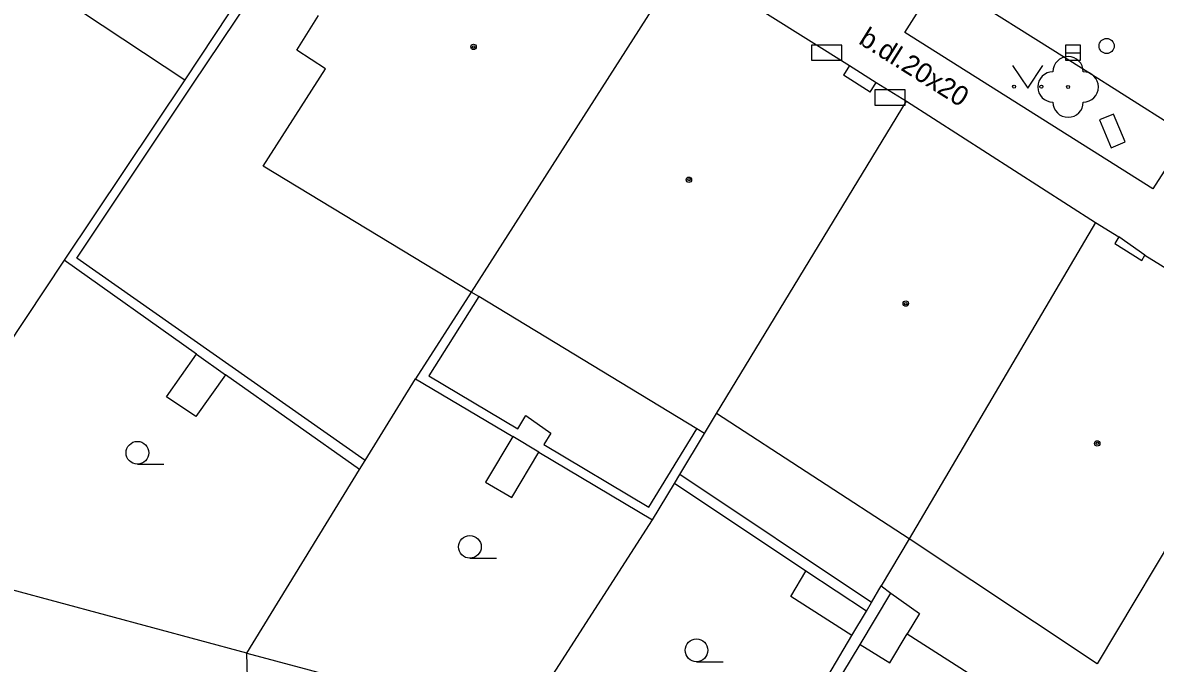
# Model space of a CAD drawing. Extents: x -595546 to -593986, y -1160845 to -1159202.
# Drawn here: x -595049.5 to -595012.16, y -1160748.75 to -1160727.63 of the extents above; entities that cross this region are included whole.
import ezdxf

# ---------------------------------------------------------------- set-up
doc = ezdxf.new("R2010")
doc.units = 0
for name, color, linetype in [('DOP - kresba z DSPS bez souradnic', 7, 'Continuous'), ('DOP - rozhrani ploch obecne', 7, 'Continuous'), ('Level 22', 7, 'Continuous'), ('Level 24', 7, 'Continuous'), ('Level 27', 7, 'Continuous'), ('Level 28', 7, 'Continuous'), ('Level 36', 7, 'Continuous'), ('Level 39', 7, 'Continuous'), ('TM - budovy zdene_ betonove - NP', 7, 'Continuous'), ('TM - budovy zdene_ betonove - VP', 7, 'Continuous'), ('TM - chodniky - VP', 7, 'Continuous'), ('TM - komunikace - VP', 7, 'Continuous'), ('TM - plot drateny_ kovovy - VP', 7, 'Continuous'), ('TM - podezdivka plotu - VP', 7, 'Continuous'), ('TM - popis povrchu', 7, 'Continuous'), ('TM - vstup do budovy - zdene_ betonove  - shora neviditelny', 7, 'Continuous')]:
    doc.layers.add(name, color=color, linetype=linetype)

msp = doc.modelspace()

# ---------------------------------------------------------------- linework, layer by layer
at = {"layer": 'DOP - kresba z DSPS bez souradnic'}
for points in [[(-595047.72, -1160735.39), (-595043.91, -1160729.69)], [(-595038.21, -1160742.06), (-595047.72, -1160735.39)], [(-595034.47, -1160736.66), (-595036.11, -1160739.27)], [(-595043.77, -1160738.56), (-595042.82, -1160739.24)], [(-595036.11, -1160739.27), (-595033.18, -1160741.02)], [(-595033.18, -1160741.02), (-595032.92, -1160740.58)], [(-595032.92, -1160740.58), (-595032.09, -1160741.16)], [(-595028.86, -1160743.6), (-595027.28, -1160741.02)], [(-595032.49, -1160741.79), (-595033.35, -1160741.27)], [(-595032.09, -1160741.16), (-595032.32, -1160741.54)], [(-595032.32, -1160741.54), (-595028.86, -1160743.6)], [(-595021.52, -1160746.74), (-595027.84, -1160742.53)], [(-595023.69, -1160745.71), (-595028.02, -1160742.82)], [(-595020.28, -1160744.65), (-595021.2, -1160746.2)], [(-595024.18, -1160746.55), (-595023.69, -1160745.71)], [(-595021.69, -1160747.03), (-595023.69, -1160745.71)], [(-595021.52, -1160746.74), (-595021.2, -1160746.2)], [(-595021.2, -1160746.2), (-595020.88, -1160746.44)], [(-595022.17, -1160747.83), (-595024.18, -1160746.55)], [(-595021.9, -1160748.13), (-595020.88, -1160746.44)], [(-595021.69, -1160747.03), (-595021.52, -1160746.74)], [(-595020.88, -1160746.44), (-595019.94, -1160747.11)], [(-595022.17, -1160747.83), (-595021.69, -1160747.03)], [(-595019.94, -1160747.11), (-595020.34, -1160747.78)], [(-595025.19, -1160752.95), (-595022.17, -1160747.83)], [(-595020.92, -1160748.73), (-595020.34, -1160747.78)], [(-595020.34, -1160747.78), (-595015.38, -1160750.95)], [(-595024.65, -1160752.69), (-595021.9, -1160748.13)], [(-595021.9, -1160748.13), (-595020.92, -1160748.73)]]:
    msp.add_lwpolyline(points, dxfattribs=at)
at = {"layer": 'DOP - rozhrani ploch obecne'}
for points in [[(-595053.74, -1160723.17), (-595044.16, -1160729.52)], [(-595044.16, -1160729.52), (-595048.14, -1160735.46)], [(-595048.14, -1160735.46), (-595054.52, -1160745.07)], [(-595043.77, -1160738.56), (-595048.14, -1160735.46)], [(-595034.72, -1160736.51), (-595036.55, -1160739.37)], [(-595044.76, -1160739.96), (-595043.77, -1160738.56)], [(-595042.82, -1160739.24), (-595043.79, -1160740.61)], [(-595038.4, -1160742.36), (-595042.82, -1160739.24)], [(-595038.21, -1160742.06), (-595036.55, -1160739.37)], [(-595036.55, -1160739.37), (-595033.35, -1160741.27)], [(-595043.79, -1160740.61), (-595044.76, -1160739.96)], [(-595033.35, -1160741.27), (-595034.25, -1160742.78)], [(-595027.84, -1160742.53), (-595027.03, -1160741.17)], [(-595033.38, -1160743.28), (-595032.49, -1160741.79)], [(-595032.49, -1160741.79), (-595028.74, -1160744.02)], [(-595038.4, -1160742.36), (-595038.21, -1160742.06)], [(-595042.11, -1160748.41), (-595038.4, -1160742.36)], [(-595028.02, -1160742.82), (-595027.84, -1160742.53)], [(-595034.25, -1160742.78), (-595033.38, -1160743.28)], [(-595028.74, -1160744.02), (-595028.02, -1160742.82)], [(-595033.11, -1160750.82), (-595028.74, -1160744.02)], [(-595042.11, -1160748.41), (-595054.52, -1160745.07)], [(-595042.11, -1160748.41), (-595033.11, -1160750.82)], [(-595041.89, -1160756.5), (-595042.11, -1160748.41)]]:
    msp.add_lwpolyline(points, dxfattribs=at)
at = {"layer": 'Level 22'}
msp.add_circle((-595015.04, -1160729.75), 0.05, dxfattribs=at)
for centre, start, end in [((-595015.04, -1160729.25), 0, 180), ((-595015.54, -1160729.75), 90, 270), ((-595014.54, -1160729.75), 270, 90), ((-595015.04, -1160730.25), 180, 0)]:
    msp.add_arc(centre, 0.5, start, end, dxfattribs=at)
at = {"layer": 'Level 24'}
for points in [[(-595023.498, -1160728.869), (-595022.498, -1160728.869), (-595022.498, -1160728.369), (-595023.498, -1160728.369)], [(-595021.407, -1160730.348), (-595020.407, -1160730.348), (-595020.407, -1160729.848), (-595021.407, -1160729.848)], [(-595014.009, -1160730.838), (-595013.618, -1160731.759), (-595013.158, -1160731.564), (-595013.548, -1160730.643)]]:
    msp.add_lwpolyline(points, close=True, dxfattribs=at)
at = {"layer": 'Level 27'}
msp.add_line((-595015.13, -1160728.62), (-595014.63, -1160728.62), dxfattribs=at)
msp.add_lwpolyline([(-595015.13, -1160728.87), (-595014.63, -1160728.87), (-595014.63, -1160728.37), (-595015.13, -1160728.37)], close=True, dxfattribs=at)
at = {"layer": 'Level 28'}
msp.add_circle((-595013.77, -1160728.4), 0.25, dxfattribs=at)
at = {"layer": 'Level 36'}
for p, q in [((-595045.72, -1160742.185), (-595044.845, -1160742.185)), ((-595034.76, -1160745.285), (-595033.885, -1160745.285)), ((-595027.29, -1160748.695), (-595026.415, -1160748.695))]:
    msp.add_line(p, q, dxfattribs=at)
msp.add_lwpolyline([(-595016.87, -1160729.04), (-595016.37, -1160729.79), (-595015.87, -1160729.04)], dxfattribs=at)
for centre, radius in [((-595016.82, -1160729.74), 0.05), ((-595015.921, -1160729.74), 0.05), ((-595045.72, -1160741.81), 0.375), ((-595034.76, -1160744.91), 0.375), ((-595027.29, -1160748.32), 0.375)]:
    msp.add_circle(centre, radius, dxfattribs=at)
at = {"layer": 'Level 39'}
for centre, radius in [((-595034.64, -1160728.43), 0.09), ((-595034.64, -1160728.43), 0.0398), ((-595027.54, -1160732.81), 0.09), ((-595027.54, -1160732.81), 0.0398), ((-595020.39, -1160736.89), 0.09), ((-595020.39, -1160736.89), 0.0398), ((-595014.08, -1160741.5), 0.09), ((-595014.08, -1160741.5), 0.0398)]:
    msp.add_circle(centre, radius, dxfattribs=at)
at = {"layer": 'TM - budovy zdene_ betonove - NP'}
for points in [[(-595022.25, -1160729.04), (-595022.44, -1160729.36)], [(-595021.56, -1160729.92), (-595021.37, -1160729.6)], [(-595013.37, -1160734.69), (-595013.5, -1160734.91)], [(-595012.61, -1160735.47), (-595012.51, -1160735.29)]]:
    msp.add_lwpolyline(points, dxfattribs=at)
at = {"layer": 'TM - budovy zdene_ betonove - VP'}
for points in [[(-595027.74, -1160725.59), (-595034.72, -1160736.51)], [(-595027.74, -1160725.59), (-595022.25, -1160729.04)], [(-595040.47, -1160728.54), (-595039.75, -1160727.4)], [(-595039.52, -1160729.15), (-595040.47, -1160728.54)], [(-595041.57, -1160732.36), (-595039.52, -1160729.15)], [(-595022.25, -1160729.04), (-595021.37, -1160729.6)], [(-595021.37, -1160729.6), (-595020.37, -1160730.22)], [(-595026.63, -1160740.51), (-595020.37, -1160730.22)], [(-595020.37, -1160730.22), (-595014.14, -1160734.22)], [(-595034.72, -1160736.51), (-595041.57, -1160732.36)], [(-595014.14, -1160734.22), (-595020.28, -1160744.65)], [(-595014.14, -1160734.22), (-595013.37, -1160734.69)], [(-595012.51, -1160735.29), (-595013.37, -1160734.69)], [(-595012.51, -1160735.29), (-595007.78, -1160738.22)], [(-595034.47, -1160736.66), (-595034.72, -1160736.51)], [(-595027.28, -1160741.02), (-595034.47, -1160736.66)], [(-595007.78, -1160738.22), (-595014.08, -1160748.77)], [(-595027.03, -1160741.17), (-595026.63, -1160740.51)], [(-595020.28, -1160744.65), (-595026.63, -1160740.51)], [(-595027.03, -1160741.17), (-595027.28, -1160741.02)], [(-595014.08, -1160748.77), (-595020.28, -1160744.65)]]:
    msp.add_lwpolyline(points, dxfattribs=at)
at = {"layer": 'TM - chodniky - VP'}
for points in [[(-595020.42, -1160727.95), (-595019.29, -1160726.16)], [(-595012.25, -1160733.11), (-595020.42, -1160727.95)], [(-595011.1, -1160731.33), (-595012.25, -1160733.11)]]:
    msp.add_lwpolyline(points, dxfattribs=at)
at = {"layer": 'TM - komunikace - VP'}
for points in [[(-595019.29, -1160726.16), (-595014.6, -1160729.12)], [(-595014.6, -1160729.12), (-595011.54, -1160731.05)]]:
    msp.add_lwpolyline(points, dxfattribs=at)
at = {"layer": 'TM - plot drateny_ kovovy - VP'}
msp.add_lwpolyline([(-595043.91, -1160729.69), (-595041.49, -1160726.07)], dxfattribs=at)
at = {"layer": 'TM - podezdivka plotu - VP'}
msp.add_lwpolyline([(-595041.75, -1160725.87), (-595044.16, -1160729.52)], dxfattribs=at)
at = {"layer": 'TM - vstup do budovy - zdene_ betonove  - shora neviditelny'}
for points in [[(-595021.56, -1160729.92), (-595022.44, -1160729.36)], [(-595013.5, -1160734.91), (-595012.61, -1160735.47)]]:
    msp.add_lwpolyline(points, dxfattribs=at)

# ---------------------------------------------------------------- texts
at = {"layer": 'TM - popis povrchu'}
msp.add_text('b.dl.20x20', height=0.65, rotation=327.9101, dxfattribs=at).set_placement((-595021.98, -1160728.3))

doc.saveas('drawing.dxf')
